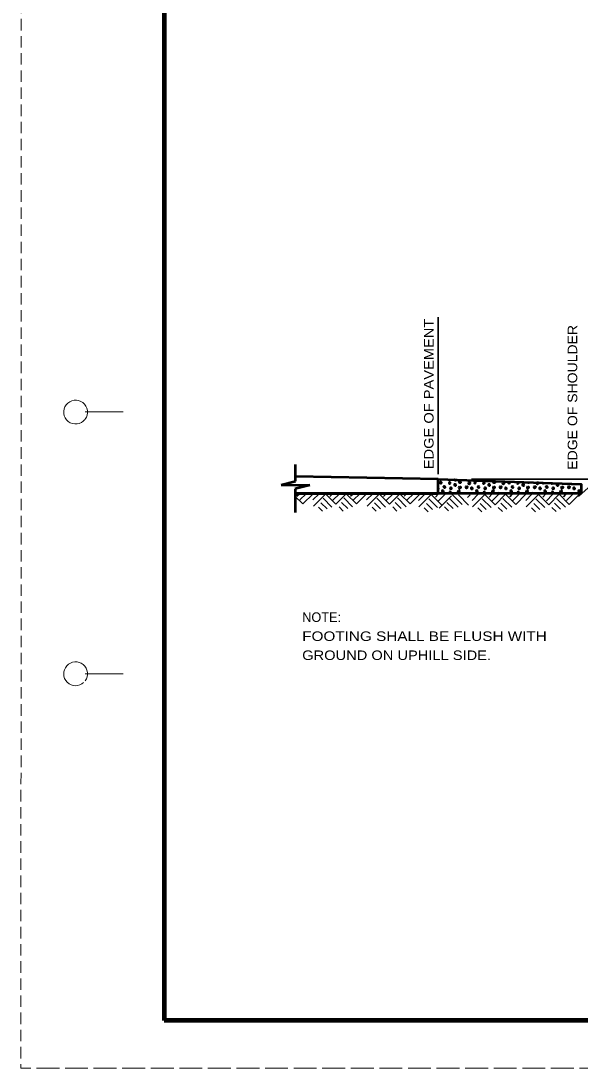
# Model space of a CAD drawing. Extents: x -2 to 678, y -1 to 439.
# Drawn here: x -2 to 115.4, y -0.7 to 219.3 of the extents above; entities that cross this region are included whole.
import ezdxf

# ---------------------------------------------------------------- set-up
doc = ezdxf.new("R2010")
doc.units = 0
doc.header["$LTSCALE"] = 0.8
doc.linetypes.add('LONG_DASHED', pattern=[7.5, 6, -1.5])
doc.linetypes.add('MEDIUM_DASHED', pattern=[4.5, 3, -1.5])
doc.layers.add('1', color=7, linetype='Continuous', lineweight=35)
doc.layers.add('61', color=7, linetype='Continuous', lineweight=35)

msp = doc.modelspace()

# ---------------------------------------------------------------- linework, layer by layer
at = {"layer": '1', "linetype": 'MEDIUM_DASHED', "lineweight": 13}
msp.add_line((-1.9245, 439.3337), (-1.9845, -0.7063), dxfattribs=at)
at = {"layer": '1'}
for p, q in [((85.6261, 124.0616), (85.6261, 157.0567)), ((92.6261, 123.0616), (144.6261, 123.0616)), ((117.8027, 121.8595), (115.0492, 119.3802)), ((55.6078, 119.4146), (57.1878, 117.8346)), ((56.4678, 119.9746), (55.9478, 119.4546)), ((57.9078, 119.9746), (56.5878, 118.6546)), ((59.3278, 119.9746), (57.1878, 117.8346)), ((60.6078, 119.9746), (59.2878, 118.6546)), ((62.0278, 119.9746), (59.4078, 117.3546)), ((61.4478, 119.0146), (63.3078, 117.1746)), ((61.9278, 119.9746), (64.1278, 117.7746)), ((63.4478, 119.9746), (62.8878, 119.3946)), ((64.8878, 119.9746), (63.5078, 118.5946)), ((66.3078, 119.9746), (64.1278, 117.7746)), ((65.7878, 119.0746), (67.6278, 117.2346)), ((66.3078, 119.9746), (68.4478, 117.8346)), ((67.7278, 119.9746), (67.2078, 119.4546)), ((69.1678, 119.9746), (67.8478, 118.6546)), ((70.5878, 119.9746), (68.4478, 117.8346)), ((71.8678, 119.9746), (70.5478, 118.6546)), ((73.2878, 119.9746), (70.6678, 117.3546)), ((72.7078, 119.0146), (74.5678, 117.1746)), ((73.1878, 119.9746), (75.3878, 117.7746)), ((74.7078, 119.9746), (74.1478, 119.3946)), ((76.1478, 119.9746), (74.7678, 118.5946)), ((77.5678, 119.9746), (75.3878, 117.7746)), ((77.0478, 119.0746), (78.8878, 117.2346)), ((77.5678, 119.9746), (79.7078, 117.8346)), ((78.9878, 119.9746), (78.4678, 119.4546)), ((80.4278, 119.9746), (79.1078, 118.6546)), ((81.8478, 119.9746), (79.7078, 117.8346)), ((82.7706, 119.8616), (81.4506, 118.5416)), ((84.1906, 119.8616), (81.5706, 117.2416)), ((83.6106, 118.9016), (85.4706, 117.0616)), ((84.0906, 119.8616), (86.2906, 117.6616)), ((85.6106, 119.8616), (85.0506, 119.2816)), ((87.0506, 119.8616), (85.6706, 118.4816)), ((88.4281, 119.5367), (85.8081, 116.9167)), ((87.9506, 118.9616), (89.7906, 117.1216)), ((88.4706, 119.8616), (90.6106, 117.7216)), ((89.8507, 119.7398), (91.9907, 117.5998)), ((92.3242, 119.7398), (91.7642, 119.1598)), ((94.0306, 119.8616), (92.7106, 118.5416)), ((95.4506, 119.8616), (92.8306, 117.2416)), ((94.8706, 118.9016), (96.7306, 117.0616)), ((95.3506, 119.8616), (97.5506, 117.6616)), ((96.8706, 119.8616), (96.3106, 119.2816)), ((98.3106, 119.8616), (96.9306, 118.4816)), ((99.7306, 119.8616), (97.5506, 117.6616)), ((99.2106, 118.9616), (101.0506, 117.1216)), ((99.7306, 119.8616), (101.8706, 117.7216)), ((101.1506, 119.8616), (100.6306, 119.3416)), ((102.5906, 119.8616), (101.2706, 118.5416)), ((104.0106, 119.8616), (101.8706, 117.7216)), ((105.2906, 119.8616), (103.9706, 118.5416)), ((106.7106, 119.8616), (104.0906, 117.2416)), ((106.1306, 118.9016), (107.9906, 117.0616)), ((106.6106, 119.8616), (108.8106, 117.6616)), ((108.1306, 119.8616), (107.5706, 119.2816)), ((109.629, 119.7803), (108.309, 118.4603)), ((110.9906, 119.8616), (108.8106, 117.6616)), ((110.4706, 118.9616), (112.3106, 117.1216)), ((110.9906, 119.8616), (113.1306, 117.7216)), ((112.4106, 119.8616), (111.8906, 119.3416)), ((113.8506, 119.8616), (112.5306, 118.5416)), ((115.2706, 119.8616), (113.1306, 117.7216)), ((60.4878, 117.1346), (61.3478, 116.2946)), ((60.9878, 118.0546), (62.2678, 116.7746)), ((64.8078, 117.1946), (65.6678, 116.3346)), ((65.3278, 118.1146), (66.6078, 116.8346)), ((71.7478, 117.1346), (72.6078, 116.2946)), ((72.2478, 118.0546), (73.5278, 116.7746)), ((76.0678, 117.1946), (76.9278, 116.3346)), ((76.5878, 118.1146), (77.8678, 116.8346)), ((82.6506, 117.0216), (83.5106, 116.1816)), ((83.1506, 117.9416), (84.4306, 116.6616)), ((86.9128, 117.184), (87.7728, 116.344)), ((87.4533, 118.1446), (88.7333, 116.8646)), ((93.9106, 117.0216), (94.7706, 116.1816)), ((94.4106, 117.9416), (95.6906, 116.6616)), ((98.2306, 117.0816), (99.0906, 116.2216)), ((98.7506, 118.0016), (100.0306, 116.7216)), ((105.1706, 117.0216), (106.0306, 116.1816)), ((105.6706, 117.9416), (106.9506, 116.6616)), ((109.4906, 117.0816), (110.3506, 116.2216)), ((110.0106, 118.0016), (111.2906, 116.7216))]:
    msp.add_line(p, q, dxfattribs=at)
at = {"layer": '1', "lineweight": 53}
for p, q in [((55.6702, 122.5845), (55.6702, 126.0845)), ((85.6261, 123.0616), (55.6702, 123.5845)), ((52.6394, 121.852), (55.6702, 122.5845)), ((52.6394, 121.852), (58.6385, 121.7472)), ((58.6385, 121.7472), (55.6078, 121.0146)), ((55.6078, 121.0146), (55.6078, 116.0146)), ((115.6078, 120.0146), (55.6078, 120.0146)), ((90.8743, 120.0943), (90.8246, 120.0146)), ((98.0343, 120.0943), (97.9846, 120.0146)), ((105.1943, 120.0943), (105.1446, 120.0146)), ((112.3543, 120.0943), (112.3046, 120.0146))]:
    msp.add_line(p, q, dxfattribs=at)
msp.add_lwpolyline([(55.6078, 120.0146), (85.6261, 120.0146), (85.6261, 123.0616), (115.6078, 122.0146), (115.6078, 120.0146), (85.6261, 120.0146), (85.6261, 123.0616), (115.6078, 122.0146), (115.6078, 120.0146), (85.6261, 120.0146)], dxfattribs=at)
for points in [[(85.6261, 121.0131), (85.6543, 121.0343), (85.6261, 121.119)], [(86.2143, 122.3942), (86.0343, 122.4142), (86.0343, 122.2343), (86.2143, 122.1743), (86.2943, 122.2343), (86.2743, 122.3542), (86.2343, 122.3542)], [(86.9943, 121.4543), (86.7543, 121.4543), (86.7743, 121.3742), (86.8943, 121.3143), (86.9943, 121.2942), (87.0543, 121.3143), (87.0143, 121.4342), (86.9543, 121.5142)], [(88.0343, 122.3942), (87.8943, 122.2343), (87.9143, 122.1542), (87.9943, 122.1542), (88.1543, 122.1942), (88.1543, 122.2942), (88.0343, 122.3542), (87.9943, 122.3542)], [(88.2943, 121.2542), (88.1543, 121.1142), (88.1743, 121.0142), (88.2543, 121.0142), (88.4143, 121.0542), (88.4143, 121.1743), (88.2943, 121.2343), (88.2543, 121.2343)], [(89.1143, 121.9543), (89.0143, 121.9142), (89.0143, 121.8143), (89.1543, 121.6942), (89.2943, 121.7343), (89.2943, 121.8542), (89.2343, 121.9142), (89.0943, 121.9342), (89.0343, 121.9342)], [(89.1003, 122.9402), (89.0543, 122.8942), (89.1543, 122.8143), (89.2543, 122.8143), (89.4143, 122.8742), (89.428, 122.9288)], [(90.0543, 121.4142), (89.9743, 121.2742), (90.0343, 121.1743), (90.1743, 121.1743), (90.2943, 121.2343), (90.3343, 121.3342), (90.1743, 121.3542), (90.0943, 121.3942)], [(90.1943, 122.5742), (90.0343, 122.5142), (90.0143, 122.3942), (90.2143, 122.3143), (90.3743, 122.3542), (90.3343, 122.4543), (90.2143, 122.5343), (90.0943, 122.5343)], [(91.4743, 121.4742), (91.3943, 121.3342), (91.4543, 121.2343), (91.5943, 121.2343), (91.7143, 121.2942), (91.7543, 121.3942), (91.5943, 121.4142), (91.5143, 121.4543)], [(92.0743, 122.3143), (91.9743, 122.1743), (92.0343, 122.0742), (92.1743, 122.0742), (92.2943, 122.1342), (92.3343, 122.2343), (92.1743, 122.2542), (92.0943, 122.2942)], [(92.7343, 121.1942), (92.5543, 121.2142), (92.5543, 121.0343), (92.7343, 120.9742), (92.8143, 121.0343), (92.7743, 121.1542), (92.7543, 121.1542)], [(93.3743, 122.3942), (93.1943, 122.4142), (93.1943, 122.2343), (93.3743, 122.1743), (93.4543, 122.2343), (93.4343, 122.3542), (93.3943, 122.3542)], [(94.1543, 121.4543), (93.9143, 121.4543), (93.9343, 121.3742), (94.0543, 121.3143), (94.1543, 121.2942), (94.2143, 121.3143), (94.1743, 121.4342), (94.1143, 121.5142)], [(95.1943, 122.3942), (95.0543, 122.2343), (95.0743, 122.1542), (95.1543, 122.1542), (95.3143, 122.1942), (95.3143, 122.2942), (95.1943, 122.3542), (95.1543, 122.3542)], [(95.4543, 121.2542), (95.3143, 121.1142), (95.3343, 121.0142), (95.4143, 121.0142), (95.5743, 121.0542), (95.5743, 121.1743), (95.4543, 121.2343), (95.4143, 121.2343)], [(96.2743, 121.9543), (96.1743, 121.9142), (96.1743, 121.8143), (96.3143, 121.6942), (96.4543, 121.7343), (96.4543, 121.8542), (96.3943, 121.9142), (96.2543, 121.9342), (96.1943, 121.9342)], [(97.2143, 121.4142), (97.1343, 121.2742), (97.1943, 121.1743), (97.3343, 121.1743), (97.4543, 121.2343), (97.4943, 121.3342), (97.3343, 121.3542), (97.2543, 121.3942)], [(97.3543, 122.5742), (97.1943, 122.5142), (97.1743, 122.3942), (97.3743, 122.3143), (97.5343, 122.3542), (97.4943, 122.4543), (97.3743, 122.5343), (97.2543, 122.5343)], [(98.6343, 121.4742), (98.5543, 121.3342), (98.6143, 121.2343), (98.7543, 121.2343), (98.8743, 121.2942), (98.9143, 121.3942), (98.7543, 121.4142), (98.6743, 121.4543)], [(99.2343, 122.3143), (99.1343, 122.1743), (99.1943, 122.0742), (99.3343, 122.0742), (99.4543, 122.1342), (99.4943, 122.2343), (99.3343, 122.2542), (99.2543, 122.2942)], [(99.8943, 121.1942), (99.7143, 121.2142), (99.7143, 121.0343), (99.8943, 120.9742), (99.9743, 121.0343), (99.9343, 121.1542), (99.9143, 121.1542)], [(100.5343, 122.3942), (100.3543, 122.4142), (100.3543, 122.2343), (100.5343, 122.1743), (100.6143, 122.2343), (100.5943, 122.3542), (100.5543, 122.3542)], [(101.3143, 121.4543), (101.0743, 121.4543), (101.0943, 121.3742), (101.2143, 121.3143), (101.3143, 121.2942), (101.3743, 121.3143), (101.3343, 121.4342), (101.2743, 121.5142)], [(102.3543, 122.3942), (102.2143, 122.2343), (102.2343, 122.1542), (102.3143, 122.1542), (102.4743, 122.1942), (102.4743, 122.2942), (102.3543, 122.3542), (102.3143, 122.3542)], [(102.6143, 121.2542), (102.4743, 121.1142), (102.4943, 121.0142), (102.5743, 121.0142), (102.7343, 121.0542), (102.7343, 121.1743), (102.6143, 121.2343), (102.5743, 121.2343)], [(103.4343, 121.9543), (103.3343, 121.9142), (103.3343, 121.8143), (103.4743, 121.6942), (103.6143, 121.7343), (103.6143, 121.8542), (103.5543, 121.9142), (103.4143, 121.9342), (103.3543, 121.9342)], [(104.3743, 121.4142), (104.2943, 121.2742), (104.3543, 121.1743), (104.4943, 121.1743), (104.6143, 121.2343), (104.6543, 121.3342), (104.4943, 121.3542), (104.4143, 121.3942)], [(104.3367, 122.4082), (104.3343, 122.3942), (104.5343, 122.3143), (104.6943, 122.3542), (104.6775, 122.3962)], [(105.7943, 121.4742), (105.7143, 121.3342), (105.7743, 121.2343), (105.9143, 121.2343), (106.0343, 121.2942), (106.0743, 121.3942), (105.9143, 121.4142), (105.8343, 121.4543)], [(106.3943, 122.3143), (106.2943, 122.1743), (106.3543, 122.0742), (106.4943, 122.0742), (106.6143, 122.1342), (106.6543, 122.2343), (106.4943, 122.2542), (106.4143, 122.2942)], [(107.0543, 121.1942), (106.8743, 121.2142), (106.8743, 121.0343), (107.0543, 120.9742), (107.1343, 121.0343), (107.0943, 121.1542), (107.0743, 121.1542)], [(107.5143, 122.2972), (107.5143, 122.2343), (107.6943, 122.1743), (107.7743, 122.2343), (107.7653, 122.2884)], [(108.4743, 121.4543), (108.2343, 121.4543), (108.2543, 121.3742), (108.3743, 121.3143), (108.4743, 121.2942), (108.5343, 121.3143), (108.4943, 121.4342), (108.4343, 121.5142)], [(109.3748, 122.2322), (109.3943, 122.1542), (109.4743, 122.1542), (109.6343, 122.1942), (109.6343, 122.2232)], [(109.7743, 121.2542), (109.6343, 121.1142), (109.6543, 121.0142), (109.7343, 121.0142), (109.8943, 121.0542), (109.8943, 121.1743), (109.7743, 121.2343), (109.7343, 121.2343)], [(110.5943, 121.9543), (110.4943, 121.9142), (110.4943, 121.8143), (110.6343, 121.6942), (110.7743, 121.7343), (110.7743, 121.8542), (110.7143, 121.9142), (110.5743, 121.9342), (110.5143, 121.9342)], [(111.5343, 121.4142), (111.4543, 121.2742), (111.5143, 121.1743), (111.6543, 121.1743), (111.7743, 121.2343), (111.8143, 121.3342), (111.6543, 121.3542), (111.5743, 121.3942)], [(112.9543, 121.4742), (112.8743, 121.3342), (112.9343, 121.2343), (113.0743, 121.2343), (113.1943, 121.2942), (113.2343, 121.3942), (113.0743, 121.4142), (112.9943, 121.4543)], [(113.5061, 122.088), (113.5143, 122.0742), (113.6543, 122.0742), (113.6703, 122.0823)], [(114.2143, 121.1942), (114.0343, 121.2142), (114.0343, 121.0343), (114.2143, 120.9742), (114.2943, 121.0343), (114.2543, 121.1542), (114.2343, 121.1542)], [(86.6743, 120.5943), (86.4343, 120.5943), (86.4543, 120.4942), (86.5743, 120.4342), (86.6743, 120.4142), (86.7143, 120.4342), (86.6943, 120.5542), (86.6343, 120.6542)], [(88.0943, 120.3542), (87.9543, 120.2142), (87.9743, 120.1142), (88.0743, 120.1142), (88.2143, 120.1542), (88.2143, 120.2742), (88.0943, 120.3342), (88.0743, 120.3342)], [(89.8343, 120.6142), (89.7543, 120.4543), (89.8143, 120.3742), (89.9543, 120.3742), (90.0743, 120.4342), (90.0943, 120.5142), (89.9543, 120.5542), (89.8743, 120.5742)], [(91.2111, 120.0146), (91.2143, 120.0343), (91.0343, 120.0343), (90.8943, 120.0542), (90.8343, 120.0542)], [(93.8343, 120.5943), (93.5943, 120.5943), (93.6143, 120.4942), (93.7343, 120.4342), (93.8343, 120.4142), (93.8743, 120.4342), (93.8543, 120.5542), (93.7943, 120.6542)], [(95.2543, 120.3542), (95.1143, 120.2142), (95.1343, 120.1142), (95.2343, 120.1142), (95.3743, 120.1542), (95.3743, 120.2742), (95.2543, 120.3342), (95.2343, 120.3342)], [(96.9943, 120.6142), (96.9143, 120.4543), (96.9743, 120.3742), (97.1143, 120.3742), (97.2343, 120.4342), (97.2543, 120.5142), (97.1143, 120.5542), (97.0343, 120.5742)], [(98.3711, 120.0146), (98.3743, 120.0343), (98.1943, 120.0343), (98.0543, 120.0542), (97.9943, 120.0542)], [(100.9943, 120.5943), (100.7543, 120.5943), (100.7743, 120.4942), (100.8943, 120.4342), (100.9943, 120.4142), (101.0343, 120.4342), (101.0143, 120.5542), (100.9543, 120.6542)], [(102.4143, 120.3542), (102.2743, 120.2142), (102.2943, 120.1142), (102.3943, 120.1142), (102.5343, 120.1542), (102.5343, 120.2742), (102.4143, 120.3342), (102.3943, 120.3342)], [(104.1543, 120.6142), (104.0743, 120.4543), (104.1343, 120.3742), (104.2743, 120.3742), (104.3943, 120.4342), (104.4143, 120.5142), (104.2743, 120.5542), (104.1943, 120.5742)], [(105.5311, 120.0146), (105.5343, 120.0343), (105.3543, 120.0343), (105.2143, 120.0542), (105.1543, 120.0542)], [(108.1543, 120.5943), (107.9143, 120.5943), (107.9343, 120.4942), (108.0543, 120.4342), (108.1543, 120.4142), (108.1943, 120.4342), (108.1743, 120.5542), (108.1143, 120.6542)], [(109.5743, 120.3542), (109.4343, 120.2142), (109.4543, 120.1142), (109.5543, 120.1142), (109.6943, 120.1542), (109.6943, 120.2742), (109.5743, 120.3342), (109.5543, 120.3342)], [(111.3143, 120.6142), (111.2343, 120.4543), (111.2943, 120.3742), (111.4343, 120.3742), (111.5543, 120.4342), (111.5743, 120.5142), (111.4343, 120.5542), (111.3543, 120.5742)], [(112.6911, 120.0146), (112.6943, 120.0343), (112.5143, 120.0343), (112.3743, 120.0542), (112.3143, 120.0542)], [(115.3143, 120.5943), (115.0743, 120.5943), (115.0943, 120.4942), (115.2143, 120.4342), (115.3143, 120.4142), (115.3543, 120.4342), (115.3343, 120.5542), (115.2743, 120.6542)]]:
    msp.add_spline(points, degree=3, dxfattribs=at)
at = {"layer": '61', "lineweight": 13}
for p, q in [((11.4955, 137.1537), (19.4955, 137.1537)), ((11.5155, 82.1337), (19.4955, 82.1337))]:
    msp.add_line(p, q, dxfattribs=at)
at = {"layer": '61', "lineweight": 158}
msp.add_line((667.1355, 9.2937), (28.0755, 9.3137), dxfattribs=at)
at = {"layer": '61', "linetype": 'LONG_DASHED', "lineweight": 13}
msp.add_line((678.0755, -0.6863), (-1.9845, -0.7063), dxfattribs=at)
at = {"layer": '61', "lineweight": 158}
msp.add_lwpolyline([(667.1155, 429.3337), (28.0755, 429.3337), (28.0755, 9.3137)], dxfattribs=at)
at = {"layer": '61', "lineweight": 13}
for centre, start, end in [((9.4933, 137.135), 322.67175, 321.71615), ((9.4933, 82.135), 323.13009, 312.31439)]:
    msp.add_arc(centre, 2.5, start, end, dxfattribs=at)

# ---------------------------------------------------------------- texts
at = {"layer": '1'}
for s, width, p in [('EDGE OF PAVEMENT', 1.15, (84.6344, 125.1307)), ('EDGE OF SHOULDER', 1.1, (114.7921, 125.0278))]:
    msp.add_text(s, height=2, rotation=90, dxfattribs=dict(at, width=width)).set_placement(p)
msp.add_text('NOTE:', height=2, dxfattribs=at).set_placement((57.0566, 93.0365))
for s, width, p in [('FOOTING SHALL BE FLUSH WITH', 1.2, (57.0566, 89.0365)), ('GROUND ON UPHILL SIDE.', 1.15, (57.0566, 85.0365))]:
    msp.add_text(s, height=2, dxfattribs=dict(at, width=width)).set_placement(p)

doc.saveas('drawing.dxf')
